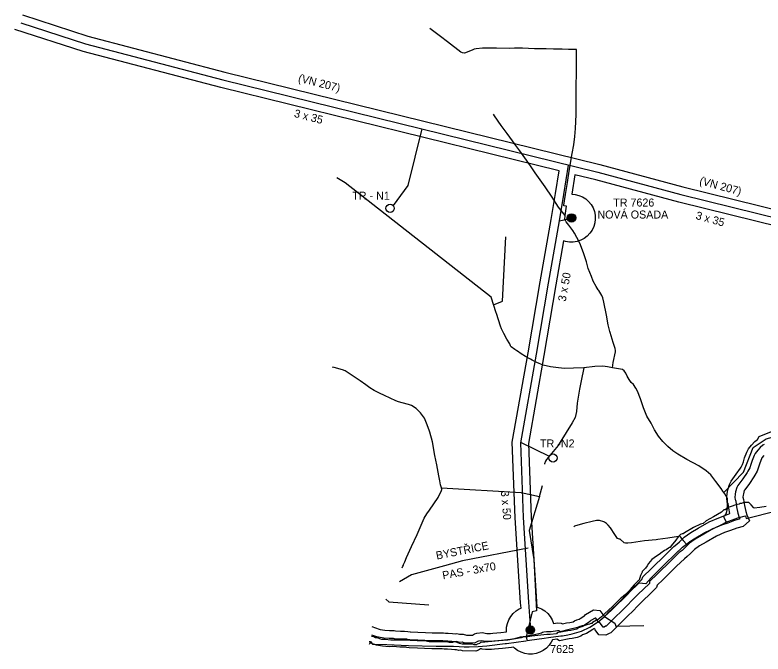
# Model space of a CAD drawing. Extents: x -439095 to -431527, y -1129525 to -1119219.
# Drawn here: x -439095 to -438161, y -1124403 to -1123605 of the extents above; entities that cross this region are included whole.
import ezdxf

# ---------------------------------------------------------------- set-up
doc = ezdxf.new("R2010")
doc.units = 0
for name, color, linetype in [('13861012_venkovní vedení elektrické sítě VN 1-35 kV_Stav', 7, 'Continuous'), ('14250012_plynovod STL_Stav', 7, 'Continuous'), ('14801013_OP vedení elektrické sítě_Stav', 7, 'Continuous'), ('Trafostanice', 7, 'Continuous'), ('Vrstva 13', 7, 'Continuous'), ('Vrstva 19', 7, 'Continuous'), ('Vrstva 21', 7, 'Continuous'), ('Vrstva 58', 7, 'Continuous')]:
    doc.layers.add(name, color=color, linetype=linetype)

msp = doc.modelspace()

# ---------------------------------------------------------------- linework, layer by layer
at = {"layer": '13861012_venkovní vedení elektrické sítě VN 1-35 kV_Stav'}
msp.add_line((-438464.02, -1124138.56), (-438428.03, -1124155.83), dxfattribs=at)
for points in [[(-439088.23, -1123614.34), (-439007.22, -1123640.64), (-438835.74, -1123685.67), (-438367.56, -1123800.96), (-438263.63, -1123828.96), (-438072.97, -1123875.97)], [(-438587.35, -1123746.84), (-438604.89, -1123817.59), (-438623.06, -1123842.59)], [(-438404.4, -1123792.3), (-438410.29, -1123829.14), (-438410.29, -1123829.15), (-438415.85, -1123861.97), (-438429.64, -1123939.97), (-438444.63, -1124028.49), (-438464.17, -1124139.38), (-438460.66, -1124232.64), (-438453.88, -1124338.49), (-438452.62, -1124356.08), (-438452.62, -1124356.09), (-438451.55, -1124372.99), (-438451.29, -1124373.35), (-438451.28, -1124373.5)], [(-438415.85, -1123861.97), (-438409.29, -1123860.54), (-438400.33, -1123858.27)], [(-438159.73, -1124141.57), (-438161.25, -1124142.38), (-438164.49, -1124145.06), (-438167.77, -1124148.6), (-438170.88, -1124152.51), (-438172.35, -1124155.27), (-438174.63, -1124161.5), (-438176.19, -1124166.38), (-438177.78, -1124170.67), (-438179.87, -1124174.71), (-438180.94, -1124176.42), (-438186.35, -1124184.31), (-438192.5, -1124192.7), (-438193.83, -1124195.21), (-438195.39, -1124200.58), (-438196.05, -1124203.67), (-438196.14, -1124207.6), (-438196, -1124210.23), (-438195.48, -1124210.94), (-438195.17, -1124212.06), (-438194.07, -1124219.42), (-438192.42, -1124227.33), (-438190.97, -1124232.78), (-438190.27, -1124234.31), (-438190.84, -1124234.82), (-438196.86, -1124236.34), (-438205.18, -1124239.55), (-438212.77, -1124242.22), (-438223.88, -1124246.96), (-438237.2, -1124254.75), (-438245.75, -1124259.66), (-438253.08, -1124264.93), (-438258.48, -1124270.33), (-438262.11, -1124273.73), (-438265.86, -1124276.55), (-438275.98, -1124286.4), (-438293.42, -1124303.41), (-438302.55, -1124312.28), (-438302.85, -1124313.1), (-438302.75, -1124314.02), (-438303, -1124314.98), (-438310.44, -1124322.14), (-438317.11, -1124328.6), (-438324.91, -1124336.52), (-438330.52, -1124342.17), (-438337.21, -1124348.83), (-438346.69, -1124357.9), (-438357.18, -1124368.4), (-438357.68, -1124368.64), (-438359.64, -1124369.6), (-438360.85, -1124369.58), (-438362.64, -1124366.81), (-438364.44, -1124364.77), (-438367.02, -1124363), (-438368.14, -1124361.12), (-438370.1, -1124358.5), (-438370.65, -1124358.46), (-438376.19, -1124361.59), (-438377.2, -1124362.79), (-438379.44, -1124364.45), (-438383.91, -1124367.24), (-438386.01, -1124368.79), (-438390.35, -1124370.16), (-438391.64, -1124370.67), (-438393.5, -1124372.16), (-438395.77, -1124372.84), (-438400.98, -1124373.87), (-438404.78, -1124374.31), (-438413.55, -1124376.09), (-438416.19, -1124374.51), (-438417.72, -1124374.37), (-438425.81, -1124375.5), (-438431.39, -1124375.53), (-438434.79, -1124375.92), (-438436.57, -1124376.42), (-438437.82, -1124377.04), (-438441.25, -1124377.9), (-438448.75, -1124379.6), (-438456.35, -1124380.91), (-438457.34, -1124381.58), (-438458.27, -1124382), (-438459.05, -1124381.94), (-438459.93, -1124381.67), (-438460.8, -1124381.66), (-438464.27, -1124382.33), (-438471.29, -1124384.36), (-438476.45, -1124385.16), (-438487.66, -1124386.53), (-438497.5, -1124387.28), (-438500.94, -1124387.74), (-438506.98, -1124387.67), (-438510.02, -1124387.25), (-438512.21, -1124386.7), (-438516.63, -1124387.2), (-438517.67, -1124387.47), (-438520.81, -1124389.41), (-438521.48, -1124389.66), (-438534.53, -1124389.49), (-438535.1, -1124389.26), (-438535.86, -1124388.65), (-438536.57, -1124388.43), (-438540.18, -1124388.78), (-438541.24, -1124388.54), (-438542.67, -1124388.07), (-438544.02, -1124387.84), (-438545.68, -1124387.9), (-438549.62, -1124387.61), (-438554.7, -1124387.34), (-438558.49, -1124387.33), (-438561.04, -1124386.93), (-438564.88, -1124386.78), (-438574.41, -1124386.96), (-438583.31, -1124386.37), (-438592.42, -1124385.91), (-438602.2, -1124385.64), (-438603.89, -1124385.39), (-438605.95, -1124384.9), (-438609.15, -1124384.74), (-438614.19, -1124384.76), (-438621.57, -1124384.15), (-438622.77, -1124383.86), (-438627.88, -1124384.09), (-438634.89, -1124383.53), (-438641.48, -1124382.36), (-438643.3, -1124381.86), (-438649.51, -1124379.72)], [(-438454.46, -1124270.9), (-438536.54, -1124286.77), (-438558.76, -1124292.96), (-438600.22, -1124304.31), (-438615.26, -1124312.96)]]:
    msp.add_lwpolyline(points, dxfattribs=at)
at = {"layer": '14250012_plynovod STL_Stav'}
for points in [[(-438206.98, -1124238.63), (-438207.31, -1124237.99), (-438209.68, -1124232.52), (-438210.03, -1124231.18), (-438208.35, -1124229.88), (-438207.24, -1124228.28), (-438206.27, -1124225.31), (-438205.6, -1124221.87), (-438205.39, -1124218.59), (-438205.38, -1124208.91), (-438208.95, -1124202.9), (-438211.18, -1124199.65), (-438213.44, -1124196.43), (-438219.91, -1124187.58), (-438226.22, -1124179.51), (-438232.16, -1124174.16), (-438241.15, -1124168.29), (-438256.12, -1124160.13), (-438267.39, -1124153.52), (-438273.87, -1124149.16), (-438279.88, -1124144.09), (-438286.38, -1124137.63), (-438291.57, -1124131.18), (-438296.51, -1124123.05), (-438301.01, -1124114.91), (-438306.3, -1124105.84), (-438310.53, -1124095.5), (-438313.97, -1124084.49), (-438317.97, -1124074.85), (-438320.09, -1124070.82), (-438322.85, -1124066.3), (-438325.76, -1124064.1), (-438328.43, -1124060.25), (-438328.45, -1124060.2), (-438328.48, -1124060.12), (-438330.86, -1124055.87), (-438332.48, -1124052.42), (-438334.63, -1124049.45), (-438336.71, -1124047.81), (-438339.25, -1124047.18), (-438348.9, -1124045.54), (-438348.28, -1124038.89), (-438345.38, -1124025.67), (-438345.49, -1124023.85), (-438345.92, -1124021.55), (-438348.43, -1124013.96), (-438352.09, -1124001.36), (-438352.42, -1124000), (-438354.4, -1123991.89), (-438356.75, -1123979.88), (-438360.08, -1123963.49), (-438361.26, -1123958.26), (-438362.47, -1123955.24), (-438363.82, -1123953.07), (-438366.34, -1123949.03), (-438366.87, -1123948.28), (-438369.46, -1123943.92), (-438373.3, -1123937.43), (-438375.49, -1123931.35), (-438379.59, -1123921.28), (-438381.61, -1123913.23), (-438385.16, -1123901.92), (-438390.07, -1123889.68), (-438393.66, -1123882.5), (-438396.73, -1123877.32), (-438398.7, -1123873.81), (-438403.66, -1123867.32), (-438406.88, -1123863.05), (-438407.78, -1123861.47), (-438408.31, -1123860.34), (-438408.64, -1123859.66), (-438408.3, -1123855.43), (-438408.25, -1123855.34), (-438406.42, -1123843.73), (-438406.67, -1123843.71), (-438409.51, -1123843.05), (-438409.81, -1123842.97), (-438409.75, -1123842.52), (-438409.72, -1123842.39), (-438407.63, -1123829.12), (-438405.27, -1123813.93), (-438403.06, -1123799.62), (-438399.32, -1123777.55), (-438397.48, -1123766.86), (-438396.04, -1123756.43), (-438395.2, -1123746.58), (-438394.54, -1123729), (-438394.59, -1123705.84), (-438394.36, -1123698.06), (-438394.42, -1123691.57), (-438394.25, -1123679.01), (-438394.2, -1123663.42), (-438394.01, -1123652.09), (-438394.01, -1123652.09), (-438393.93, -1123647.78), (-438398.72, -1123647.69), (-438403.99, -1123647.59), (-438411.96, -1123647.4), (-438414.67, -1123647.28), (-438416.76, -1123647.28), (-438422.68, -1123647.2), (-438431.88, -1123647.07), (-438439.13, -1123646.98), (-438441.33, -1123646.99), (-438446.54, -1123646.82), (-438461.52, -1123646.12), (-438465.53, -1123646.15), (-438471.33, -1123646.24), (-438478.07, -1123646.28), (-438494.05, -1123645.86), (-438511.39, -1123646.09), (-438519.36, -1123646.73), (-438521.82, -1123647.41), (-438524.19, -1123648.62), (-438534.05, -1123652.24), (-438536.59, -1123652.07), (-438538.5, -1123650.98), (-438555, -1123638.1), (-438563.84, -1123631.64), (-438577.05, -1123621.48)], [(-438408.25, -1123855.34), (-438416.53, -1123844.85), (-438424.47, -1123832.44), (-438433.3, -1123819.27), (-438445.58, -1123801.82), (-438451.49, -1123793.27), (-438458.79, -1123782.93), (-438464.91, -1123774.38), (-438469.79, -1123767.78), (-438474.14, -1123761.8), (-438480.62, -1123752.7), (-438488.26, -1123742.54), (-438496.28, -1123730.79), (-438497.91, -1123728.69)], [(-438494.46, -1123976.81), (-438500.68, -1123957.08), (-438683.04, -1123814.28), (-438693.59, -1123807.95)], [(-438497.57, -1123966.94), (-438486.39, -1123962.28), (-438482.43, -1123881.88)], [(-438348.9, -1124045.54), (-438355.36, -1124044.32), (-438361.03, -1124043.62), (-438371.16, -1124044.13), (-438384.78, -1124045.52), (-438397.98, -1124046.07), (-438408.99, -1124046.3), (-438416.44, -1124045.57), (-438426.48, -1124044.41), (-438435.87, -1124042.12), (-438443.49, -1124039.07), (-438449.57, -1124035.89), (-438451.55, -1124034.86), (-438457.67, -1124031.28), (-438463.03, -1124027.93), (-438467.95, -1124024.69), (-438468.49, -1124024.39), (-438471.13, -1124022.54), (-438475.63, -1124019.41), (-438475.9, -1124019), (-438476.32, -1124018), (-438477.44, -1124015.75), (-438481.23, -1124009.81), (-438484.76, -1124002.63), (-438487.61, -1123996.81), (-438488.81, -1123993.41), (-438491.27, -1123985.58), (-438494.14, -1123977.51), (-438494.46, -1123976.81), (-438494.8, -1123976.37)], [(-438611.98, -1124295.6), (-438611.01, -1124293.59), (-438610.3, -1124292.13), (-438610.02, -1124291.46), (-438608.61, -1124288.18), (-438606.17, -1124282.5), (-438600.02, -1124268.85), (-438593.18, -1124253.8), (-438586.66, -1124239.25), (-438584.12, -1124233.54), (-438580.97, -1124228.1), (-438577.55, -1124223.36), (-438566.79, -1124207.47), (-438562.46, -1124198.79), (-438562.34, -1124197.5), (-438562.81, -1124195.62), (-438563.95, -1124191.94), (-438564.89, -1124186.64), (-438565.95, -1124180.62), (-438568.31, -1124166.74), (-438571.02, -1124155.36), (-438574.11, -1124137.91), (-438577.28, -1124125.87), (-438577.88, -1124123.63), (-438581.44, -1124114.68), (-438584.01, -1124108.57), (-438588.98, -1124101.68), (-438594.14, -1124096.42), (-438600.12, -1124092.65), (-438604, -1124091.32), (-438611.99, -1124089.41), (-438616.32, -1124088), (-438619.76, -1124086.64), (-438633.77, -1124080.35), (-438639.91, -1124077.33), (-438646.77, -1124073.88), (-438652.27, -1124070.47), (-438657.36, -1124066.91), (-438664.23, -1124061.87), (-438676.61, -1124053.33), (-438682.81, -1124049.48), (-438686.13, -1124048.03), (-438696.57, -1124044.98), (-438698.73, -1124044.93), (-438698.75, -1124045.09)], [(-438384.78, -1124045.52), (-438388.19, -1124061.8), (-438390.22, -1124072.41), (-438393.2, -1124089.61), (-438394.14, -1124100.33), (-438395.74, -1124107.6), (-438399.34, -1124114.39), (-438414.52, -1124138.69), (-438416.92, -1124142.58), (-438431.45, -1124160.06), (-438432.62, -1124162.43), (-438433.86, -1124165.7), (-438433.84, -1124165.88)], [(-438210.06, -1124201.28), (-438185.4, -1124176.11), (-438173.41, -1124145.17), (-438156.99, -1124134.43), (-438095.98, -1124117.57)], [(-438562.81, -1124195.62), (-438463.1, -1124201.21), (-438440.37, -1124206.25), (-438436.53, -1124192.7)], [(-438440.37, -1124206.25), (-438453.11, -1124248.71), (-438447.29, -1124284.97), (-438443.96, -1124349.11), (-438449.54, -1124350.56), (-438456.94, -1124381.69), (-438456.2, -1124385.75)], [(-438653.02, -1124387.55), (-438651.91, -1124387.71), (-438651.67, -1124387.53), (-438651.46, -1124387.63), (-438648.8, -1124390.79), (-438646.01, -1124390.78), (-438631.05, -1124391.27), (-438603.82, -1124392.47), (-438569.46, -1124393.49), (-438547.87, -1124393.68), (-438540.72, -1124393.94), (-438534.45, -1124394.17), (-438534.19, -1124394.18), (-438528, -1124394.41), (-438516.72, -1124394.05), (-438505.99, -1124393.22), (-438483.22, -1124390.22), (-438481.54, -1124389.99), (-438457.2, -1124386.65), (-438455.64, -1124386.43), (-438452.59, -1124386), (-438434.26, -1124383.43), (-438429.15, -1124382.78), (-438413.51, -1124380.77), (-438411.63, -1124380.53), (-438405.01, -1124379.2), (-438399.39, -1124378.07), (-438387.96, -1124374.57), (-438377.57, -1124369.59), (-438368.91, -1124364.39), (-438367.27, -1124363.39), (-438359.31, -1124356.82), (-438350.39, -1124348.68), (-438329.27, -1124327.48), (-438328.12, -1124326.33), (-438315.69, -1124314.48), (-438315.29, -1124314.52), (-438308, -1124315.36), (-438307.67, -1124315.37), (-438300.65, -1124308.18), (-438284.26, -1124291.39), (-438270.47, -1124278.01), (-438261.49, -1124269.93), (-438256.66, -1124266.09), (-438252.43, -1124262.73), (-438251.88, -1124262.29), (-438247.26, -1124259.15), (-438233.92, -1124251.4), (-438222.01, -1124245.82), (-438212.65, -1124241.53), (-438207.77, -1124239.1), (-438206.98, -1124238.63), (-438192.51, -1124233.19), (-438182.87, -1124230.5), (-438181.97, -1124233.91), (-438144.24, -1124224.41)], [(-438256.66, -1124266.09), (-438256.98, -1124265.67), (-438260.37, -1124261.73), (-438260.5, -1124261.56), (-438260.62, -1124261.39), (-438260.77, -1124261.19), (-438262.14, -1124259.37), (-438262.34, -1124259.06), (-438262.45, -1124258.88), (-438262.57, -1124258.7), (-438264.3, -1124256.85), (-438265.18, -1124255.95), (-438266.51, -1124256.26), (-438280.11, -1124258.65), (-438292.59, -1124260.24), (-438294.75, -1124260.52), (-438309.24, -1124261.97), (-438325.35, -1124264.22), (-438329.8, -1124264.58), (-438332.08, -1124264.88), (-438332.78, -1124264.77), (-438334.34, -1124264.53), (-438339.73, -1124259.85), (-438339.86, -1124259.75), (-438340.39, -1124259.62), (-438341.72, -1124259.28), (-438342.88, -1124258.88), (-438346.22, -1124253.89), (-438351.6, -1124245.66), (-438354.34, -1124242.29), (-438356.62, -1124240.09), (-438358.91, -1124238.37), (-438359.86, -1124238.03), (-438365.3, -1124236.38), (-438369.28, -1124236.43), (-438374.42, -1124237.73), (-438384.75, -1124240.22), (-438395.24, -1124242.92), (-438396.36, -1124243.52), (-438397.23, -1124244.3)], [(-438632.18, -1124334.88), (-438628.53, -1124338.06), (-438578.66, -1124341.85)], [(-438359.18, -1124356.25), (-438346.28, -1124364.58), (-438345.05, -1124368.59), (-438309.93, -1124367.66)]]:
    msp.add_lwpolyline(points, dxfattribs=at)
at = {"layer": '14801013_OP vedení elektrické sítě_Stav'}
for points in [[(-439086.08, -1123604.53), (-439004.4, -1123631.04), (-438833.27, -1123675.98), (-438365.06, -1123791.27), (-438261.13, -1123819.28), (-438070.53, -1123866.27), (-437988.14, -1123887.48)], [(-438415.66, -1123799.41), (-438838.2, -1123695.36), (-439010.03, -1123650.24), (-439095.38, -1123622.54)], [(-438463.37, -1124345.98), (-438463.86, -1124339.17), (-438470.65, -1124233.15), (-438474.2, -1124138.69), (-438454.48, -1124026.79), (-438439.49, -1123938.26), (-438425.7, -1123860.26), (-438420.16, -1123827.52), (-438415.66, -1123799.41)], [(-438396.17, -1123804.21), (-438400.07, -1123828.55)], [(-437892.75, -1123947.93), (-437892.82, -1123947.87), (-437938.91, -1123922.24), (-437979.96, -1123910.23), (-438075.42, -1123885.67), (-438266.12, -1123838.65), (-438370.06, -1123810.64), (-438396.17, -1123804.21)], [(-438400.07, -1123828.55), (-438395.73, -1123828.9), (-438391.04, -1123830.05), (-438386.6, -1123831.95), (-438382.52, -1123834.53), (-438378.91, -1123837.73), (-438375.85, -1123841.47), (-438373.44, -1123845.65), (-438371.73, -1123850.16), (-438370.76, -1123854.89), (-438370.57, -1123859.72), (-438371.15, -1123864.51), (-438372.49, -1123869.15), (-438374.56, -1123873.51), (-438377.3, -1123877.48), (-438380.65, -1123880.96), (-438384.51, -1123883.87), (-438388.78, -1123886.11), (-438393.36, -1123887.64), (-438398.13, -1123888.41), (-438402.96, -1123888.41), (-438407.72, -1123887.64), (-438410.09, -1123886.85)], [(-438410.09, -1123886.85), (-438419.79, -1123941.67), (-438434.77, -1124030.2), (-438454.13, -1124140.07), (-438450.67, -1124232.14), (-438443.91, -1124337.81), (-438443.42, -1124344.63)], [(-438422.75, -1124364.97), (-438417.96, -1124364.31), (-438413.01, -1124364.76), (-438411.74, -1124365.52), (-438406.35, -1124364.43), (-438402.53, -1124363.98), (-438398.22, -1124363.13), (-438396.72, -1124361.92), (-438393.7, -1124360.73), (-438390.61, -1124359.76), (-438389.54, -1124358.96), (-438385.07, -1124356.18), (-438384.1, -1124355.45), (-438382.68, -1124353.77), (-438372.94, -1124348.27), (-438364.83, -1124348.86), (-438359.82, -1124355.55), (-438359.55, -1124356), (-438359.18, -1124356.25), (-438353.68, -1124350.75), (-438344.19, -1124341.67), (-438337.6, -1124335.1), (-438332.02, -1124329.49), (-438324.15, -1124321.5), (-438317.39, -1124314.95), (-438312.43, -1124310.17), (-438311.16, -1124306.7), (-438300.4, -1124296.24), (-438282.96, -1124279.24), (-438272.38, -1124268.94), (-438268.55, -1124266.06), (-438265.44, -1124263.14), (-438259.58, -1124257.28), (-438251.17, -1124251.24), (-438242.21, -1124246.1), (-438228.38, -1124238.01), (-438216.4, -1124232.89), (-438208.64, -1124230.17), (-438202.53, -1124227.81), (-438203.92, -1124221.18), (-438204.83, -1124215.1), (-438205.83, -1124213.74), (-438206.15, -1124207.75), (-438206.03, -1124202.5), (-438205.09, -1124198.14), (-438203.15, -1124191.43), (-438201, -1124187.37), (-438194.51, -1124178.53), (-438189.31, -1124170.94), (-438188.56, -1124169.75), (-438186.94, -1124166.62), (-438185.65, -1124163.12), (-438184.09, -1124158.26), (-438181.5, -1124151.18), (-438179.28, -1124147), (-438175.36, -1124142.08), (-438171.37, -1124137.78), (-438168.13, -1124135.09), (-438166.03, -1124131.26), (-438150.49, -1124125.35)], [(-438160.18, -1124155.12), (-438162.48, -1124158.02), (-438163.2, -1124159.36), (-438165.17, -1124164.74), (-438166.73, -1124169.64), (-438168.62, -1124174.72), (-438171.18, -1124179.67), (-438172.57, -1124181.9), (-438178.19, -1124190.09), (-438184, -1124198.03), (-438184.51, -1124198.99), (-438185.69, -1124203.02), (-438186.07, -1124204.84), (-438186.13, -1124207.24), (-438185.37, -1124209.98), (-438184.22, -1124217.66), (-438182.69, -1124225.02), (-438181.52, -1124229.39), (-438178.11, -1124236.85), (-438186.01, -1124243.91), (-438193.83, -1124245.89), (-438201.72, -1124248.93), (-438209.14, -1124251.55), (-438219.38, -1124255.91), (-438232.19, -1124263.4), (-438240.33, -1124268.08), (-438246.58, -1124272.58), (-438251.52, -1124277.52), (-438255.67, -1124281.4), (-438259.34, -1124284.16), (-438269, -1124293.56), (-438286.44, -1124310.58), (-438293.24, -1124317.18), (-438294.03, -1124320.23), (-438303.49, -1124329.33), (-438310.07, -1124335.7), (-438317.8, -1124343.55), (-438323.44, -1124349.24), (-438330.23, -1124355.99), (-438339.7, -1124365.05), (-438351.31, -1124376.68), (-438353.32, -1124377.64), (-438357.4, -1124379.64), (-438366.35, -1124379.49), (-438370.63, -1124372.87), (-438371.12, -1124372.32), (-438372.23, -1124371.55), (-438373.81, -1124372.72), (-438378.28, -1124375.52), (-438381.41, -1124377.82), (-438386.64, -1124379.47), (-438388.77, -1124381.18), (-438393.36, -1124382.56), (-438399.43, -1124383.76), (-438403.21, -1124384.19), (-438415.36, -1124386.66), (-438418.78, -1124384.61), (-438424.08, -1124385.36)], [(-438443.42, -1124344.63), (-438442.02, -1124344.97), (-438437.58, -1124346.87), (-438433.5, -1124349.45), (-438429.88, -1124352.65), (-438426.83, -1124356.39), (-438424.42, -1124360.57), (-438422.75, -1124364.97)], [(-438481.37, -1124375.69), (-438481.5, -1124374.64), (-438481.3, -1124369.81), (-438480.34, -1124365.08), (-438478.62, -1124360.57), (-438476.21, -1124356.39), (-438473.16, -1124352.65), (-438469.54, -1124349.45), (-438465.46, -1124346.87), (-438463.37, -1124345.98)], [(-438649.79, -1124369.05), (-438640.34, -1124372.3), (-438639.28, -1124372.59), (-438633.61, -1124373.6), (-438627.71, -1124374.07), (-438621.8, -1124373.81), (-438619.97, -1124374.25), (-438613.8, -1124374.76), (-438608.92, -1124374.74), (-438604.53, -1124374.96), (-438602, -1124375.56), (-438601.33, -1124375.66), (-438592.03, -1124375.92), (-438582.73, -1124376.39), (-438574.17, -1124376.95), (-438564.78, -1124376.78), (-438560.07, -1124376.96), (-438557.7, -1124377.33), (-438554.42, -1124377.34), (-438548.99, -1124377.63), (-438545.49, -1124377.89), (-438543.35, -1124377.81), (-438540.26, -1124378.34), (-438539.31, -1124378.65), (-438535.53, -1124378.28), (-438531.51, -1124379.53), (-438524, -1124379.63), (-438521.64, -1124378.17), (-438518.46, -1124377.34), (-438511.53, -1124376.56), (-438508.11, -1124377.42), (-438506.23, -1124377.68), (-438501.55, -1124377.73), (-438498.54, -1124377.33), (-438488.65, -1124376.58), (-438481.37, -1124375.69)], [(-438472.57, -1124394.68), (-438475.08, -1124395.07), (-438486.67, -1124396.48), (-438496.46, -1124397.23), (-438500.33, -1124397.75), (-438507.73, -1124397.66), (-438511.93, -1124397.08), (-438512.89, -1124396.84), (-438514.02, -1124396.97), (-438516.39, -1124398.43), (-438519.74, -1124399.68), (-438536.53, -1124399.46), (-438538.51, -1124398.67), (-438540.82, -1124398.89), (-438543.91, -1124398.19), (-438544.86, -1124397.88), (-438545.87, -1124397.91), (-438550.25, -1124397.59), (-438554.98, -1124397.34), (-438559.28, -1124397.33), (-438562.01, -1124396.9), (-438564.98, -1124396.78), (-438574.65, -1124396.97), (-438583.89, -1124396.35), (-438592.81, -1124395.9), (-438603.07, -1124395.62), (-438605.78, -1124395.22), (-438607.37, -1124394.84), (-438609.38, -1124394.74), (-438614.58, -1124394.76), (-438623.17, -1124394.05), (-438623.74, -1124393.91), (-438628.05, -1124394.11), (-438636.17, -1124393.46), (-438643.68, -1124392.13), (-438646.26, -1124391.42), (-438652.06, -1124389.42), (-438652.32, -1124389.89), (-438653.13, -1124391.22)], [(-438424.08, -1124385.36), (-438425.54, -1124388.43), (-438428.28, -1124392.4), (-438431.63, -1124395.89), (-438435.49, -1124398.79), (-438439.76, -1124401.03), (-438444.34, -1124402.56), (-438449.11, -1124403.33), (-438453.93, -1124403.33), (-438458.7, -1124402.56), (-438463.28, -1124401.03), (-438467.55, -1124398.79), (-438471.41, -1124395.89), (-438472.57, -1124394.68)]]:
    msp.add_lwpolyline(points, dxfattribs=at)
at = {"layer": 'Trafostanice'}
for centre, radius in [((-438400.33, -1123858.27), 5.25), ((-438400.33, -1123858.27), 4.55), ((-438400.33, -1123858.27), 3.85), ((-438400.33, -1123858.27), 3.15), ((-438400.33, -1123858.27), 2.45), ((-438400.33, -1123858.27), 1.75), ((-438400.33, -1123858.27), 1.05), ((-438400.33, -1123858.27), 0.35), ((-438451.64, -1124373.28), 5.25), ((-438451.64, -1124373.28), 4.55), ((-438451.64, -1124373.28), 3.85), ((-438451.64, -1124373.28), 3.15), ((-438451.64, -1124373.28), 2.45), ((-438451.64, -1124373.28), 1.75), ((-438451.64, -1124373.28), 1.05), ((-438451.64, -1124373.28), 0.35)]:
    msp.add_circle(centre, radius, dxfattribs=at)
at = {"layer": 'Vrstva 19'}
for centre in [(-438626.84, -1123846.23), (-438423.39, -1124158.28)]:
    msp.add_circle(centre, 5.25, dxfattribs=at)
at = {"layer": 'Vrstva 58'}
for points in [[(-438176, -1124217), (-438179, -1124214), (-438180, -1124214), (-438182, -1124214), (-438185, -1124214), (-438188, -1124215), (-438190, -1124215), (-438191, -1124216), (-438195, -1124217), (-438201, -1124219), (-438205, -1124220), (-438207, -1124222), (-438208, -1124223), (-438210, -1124223), (-438211, -1124224), (-438213, -1124226), (-438223, -1124232), (-438232, -1124237), (-438236, -1124240), (-438239, -1124241), (-438248, -1124245), (-438259, -1124252), (-438261, -1124253), (-438262, -1124253), (-438264, -1124254), (-438264, -1124254), (-438267, -1124257), (-438270, -1124261), (-438276, -1124268), (-438277, -1124270), (-438278, -1124270), (-438279, -1124271), (-438282, -1124273), (-438284, -1124274), (-438286, -1124275), (-438287, -1124276), (-438291, -1124279), (-438294, -1124281), (-438300, -1124285), (-438304, -1124290), (-438306, -1124293), (-438308, -1124296), (-438310, -1124298), (-438311, -1124299), (-438312, -1124300), (-438312, -1124301), (-438314, -1124305), (-438315, -1124308), (-438316, -1124311), (-438316, -1124311), (-438317, -1124312), (-438322, -1124317), (-438325, -1124320), (-438328, -1124324), (-438333, -1124329), (-438338, -1124333), (-438339, -1124334), (-438346, -1124341), (-438349, -1124344), (-438359, -1124353), (-438362, -1124356), (-438363, -1124357), (-438363, -1124357), (-438367, -1124360), (-438369, -1124361), (-438374, -1124364), (-438374, -1124364), (-438375, -1124365), (-438376, -1124365), (-438378, -1124366), (-438381, -1124367), (-438385, -1124368), (-438387, -1124368), (-438390, -1124369), (-438393, -1124370), (-438405, -1124373), (-438413, -1124375), (-438415, -1124376), (-438418, -1124377), (-438419, -1124378), (-438427, -1124379), (-438431, -1124379), (-438450, -1124381), (-438455, -1124382), (-438460, -1124382), (-438463, -1124383), (-438480, -1124386), (-438491, -1124387), (-438513, -1124389), (-438514, -1124389), (-438515, -1124390)], [(-438157, -1124219), (-438165, -1124220), (-438172, -1124221), (-438173, -1124220), (-438176, -1124217)], [(-438515, -1124390), (-438518, -1124391), (-438519, -1124392), (-438522, -1124392), (-438524, -1124391), (-438527, -1124391), (-438529, -1124391), (-438534, -1124391), (-438537, -1124391), (-438540, -1124390), (-438543, -1124389), (-438547, -1124388), (-438549, -1124389), (-438552, -1124389), (-438553, -1124389), (-438557, -1124388), (-438571, -1124388), (-438578, -1124388), (-438584, -1124387), (-438589, -1124387), (-438593, -1124387), (-438611, -1124386), (-438613, -1124386), (-438617, -1124386), (-438621, -1124386), (-438623, -1124386), (-438626, -1124386), (-438633, -1124385), (-438637, -1124385), (-438643, -1124383), (-438645, -1124383), (-438647, -1124382), (-438650.24, -1124381.35)]]:
    msp.add_lwpolyline(points, dxfattribs=at)

# ---------------------------------------------------------------- texts
at = {"layer": 'Vrstva 13'}
for s, rotation, p in [('(VN 207)', 345.67636, (-438742.37, -1123687.73)), ('3 x 35', 345.67629, (-438747.48, -1123731.9)), ('(VN 207)', 344.56954, (-438241.26, -1123815.94)), ('3 x 35', 344.56967, (-438245.87, -1123859.41)), ('3 x 50', 79.58638, (-438407.58, -1123963.25)), ('3 x 50', 274.99399, (-438488.56, -1124199.69)), ('BYSTŘICE', 11.28226, (-438568.55, -1124285.32)), ('PAS - 3x70', 10.16684, (-438560.68, -1124310.05))]:
    msp.add_text(s, height=10, rotation=rotation, dxfattribs=at).set_placement(p)
for s, p in [('TR 7626', (-438348.18, -1123843.99)), ('NOVÁ OSADA', (-438367.92, -1123858.99)), ('7625', (-438426.92, -1124402.06))]:
    msp.add_text(s, height=10, dxfattribs=at).set_placement(p)
at = {"layer": 'Vrstva 21'}
for s, p in [('TR - N1', (-438674.06, -1123835.49)), ('TR -N2', (-438439.59, -1124145.1))]:
    msp.add_text(s, height=10, dxfattribs=at).set_placement(p)

doc.saveas('drawing.dxf')
